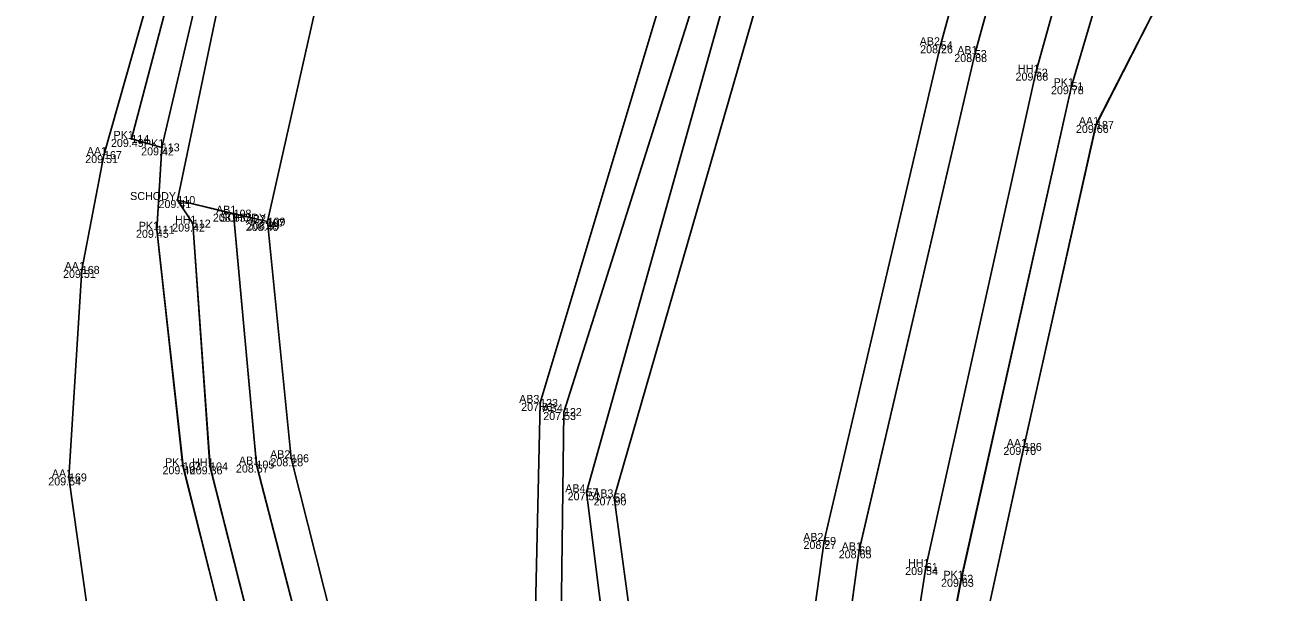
# Model space of a CAD drawing. Extents: x -262982 to -262706, y -1238714 to -1237093.
# Drawn here: x -262957.98 to -262926.85, y -1238375.85 to -1238361.66 of the extents above; entities that cross this region are included whole.
import ezdxf

# ---------------------------------------------------------------- set-up
doc = ezdxf.new("R2010")
doc.units = 0
for name, color, linetype in [('01_Hrana_betónu', 7, 'Continuous'), ('02_Oplotenie', 7, 'Continuous'), ('03_Asfalt', 7, 'Continuous'), ('05_Hrana_terénu', 7, 'Continuous'), ('06_Schody', 7, 'Continuous'), ('Groma (21)', 7, 'Continuous'), ('Groma (22)', 7, 'Continuous'), ('Groma (23)', 7, 'Continuous'), ('Groma (24)', 7, 'Continuous'), ('U002_Asfalt', 7, 'Continuous'), ('U002_Betónové panely', 7, 'Continuous'), ('U002_Schody', 7, 'Continuous'), ('U002_Zeleň_mimo', 7, 'Continuous'), ('U002_Zeleň_vnútro', 7, 'Continuous'), ('U002_Zeleň_zatrávňovač', 7, 'Continuous')]:
    doc.layers.add(name, color=color, linetype=linetype)

msp = doc.modelspace()

# ---------------------------------------------------------------- linework, layer by layer
at = {"layer": '01_Hrana_betónu'}
for points in [[(-262944.213, -1238387.387), (-262944.634, -1238381.789), (-262944.5, -1238371.343), (-262941.2, -1238360.927), (-262935.086, -1238341.218), (-262927.632, -1238317.179), (-262920.793, -1238295.265), (-262911.171, -1238262.813), (-262915.352, -1238261.064), (-262915.337, -1238259.329), (-262909.866, -1238261.629), (-262904.904, -1238263.716)], [(-262916.095, -1238261.519), (-262911.974, -1238263.293), (-262921.591, -1238294.909), (-262928.534, -1238317.073), (-262935.896, -1238340.99), (-262941.971, -1238360.685), (-262945.096, -1238371.115), (-262945.34, -1238381.803), (-262945.412, -1238387.557)], [(-262941.714, -1238387.032), (-262942.991, -1238380.859), (-262943.934, -1238373.35), (-262940.485, -1238361.041), (-262934.456, -1238341.421), (-262927.277, -1238318.134), (-262920.116, -1238294.802), (-262913.64, -1238273.614), (-262910.214, -1238263.245), (-262905.769, -1238265.099), (-262904.904, -1238263.716)], [(-262905.769, -1238265.099), (-262909.81, -1238264.181), (-262912.956, -1238273.861), (-262919.396, -1238295.066), (-262926.538, -1238318.409), (-262933.693, -1238341.579), (-262939.683, -1238361.151), (-262943.246, -1238373.477), (-262942.259, -1238380.752), (-262940.526, -1238386.713)], [(-262905.769, -1238265.099), (-262909.014, -1238275.12), (-262915.393, -1238296.189), (-262922.597, -1238319.497), (-262929.796, -1238342.936), (-262935.083, -1238362.17), (-262937.995, -1238374.567), (-262938.788, -1238380.26), (-262939.46, -1238386.668), (-262940.526, -1238386.713), (-262940.498, -1238386.859)], [(-262940.36, -1238387.407), (-262939.388, -1238387.391), (-262938.822, -1238386.902), (-262937.88, -1238380.385), (-262937.119, -1238374.802), (-262934.23, -1238362.39), (-262928.952, -1238343.2), (-262921.717, -1238319.813), (-262915.107, -1238298.192), (-262908.208, -1238275.423), (-262904.855, -1238265.436)], [(-262945.333, -1238387.95), (-262946.617, -1238387.98), (-262947.712, -1238387.066), (-262949.402, -1238383.422), (-262952.187, -1238372.656), (-262952.759, -1238366.382)], [(-262951.91, -1238366.581), (-262951.321, -1238372.499), (-262948.634, -1238383.126), (-262947.098, -1238386.578), (-262946.426, -1238387.428), (-262945.412, -1238387.557)]]:
    msp.add_lwpolyline(points, dxfattribs=at)
at = {"layer": '02_Oplotenie'}
msp.add_lwpolyline([(-262939.39, -1238320.83), (-262941.19, -1238324.79), (-262946.68, -1238336.9), (-262951.035, -1238350.68), (-262953.195, -1238358.97), (-262953.815, -1238358.809), (-262955.312, -1238364.513), (-262954.553, -1238364.724), (-262954.681, -1238366.785), (-262954.024, -1238372.698), (-262953.142, -1238376.2), (-262951.104, -1238384.342), (-262949.016, -1238390.045), (-262944.443, -1238389.969), (-262936.906, -1238389.616), (-262935.581, -1238380.82), (-262934.566, -1238375.513), (-262931.812, -1238363.194), (-262926.159, -1238344.076), (-262918.903, -1238320.384), (-262912.242, -1238298.942), (-262905.326, -1238276.054), (-262902.598, -1238266.292), (-262902.107, -1238264.892)], dxfattribs=at)
at = {"layer": '03_Asfalt'}
msp.add_lwpolyline([(-262929.61, -1238361.054), (-262931.199, -1238364.162), (-262933.003, -1238372.216), (-262934.974, -1238381.221), (-262935.119, -1238384.027), (-262936.052, -1238388.803), (-262936.611, -1238390.144), (-262937.981, -1238391.744), (-262940.017, -1238393.235), (-262941.857, -1238393.766), (-262943.351, -1238393.675), (-262945.246, -1238393.033), (-262947.034, -1238391.969), (-262949.331, -1238390.232), (-262950.782, -1238388.665), (-262952.605, -1238386.269), (-262954.108, -1238383.642), (-262955.193, -1238380.77), (-262956.048, -1238377.869), (-262956.307, -1238376.99), (-262956.874, -1238372.978), (-262956.554, -1238367.788), (-262955.999, -1238364.917), (-262954.725, -1238360.416)], dxfattribs=at)
at = {"layer": '05_Hrana_terénu'}
msp.add_lwpolyline([(-262920.126, -1238320.151), (-262927.385, -1238343.686), (-262932.704, -1238362.854), (-262935.453, -1238375.219), (-262936.279, -1238380.57), (-262937.519, -1238387.253), (-262938.314, -1238388.733), (-262939.759, -1238389.403), (-262945.681, -1238389.45), (-262947.587, -1238388.865), (-262949.049, -1238387.288), (-262950.436, -1238384.21), (-262953.347, -1238372.702), (-262953.777, -1238366.63), (-262954.163, -1238366.041), (-262952.487, -1238358.01), (-262951.855, -1238357.25), (-262949.897, -1238349.853), (-262950.29, -1238348.92), (-262949.45, -1238345.83), (-262948.76, -1238345.496), (-262946.63, -1238339.15), (-262945.04, -1238334.12), (-262941.75, -1238326.63)], dxfattribs=at)
at = {"layer": '06_Schody'}
msp.add_lwpolyline([(-262951.91, -1238366.581), (-262952.759, -1238366.382), (-262954.163, -1238366.041), (-262952.487, -1238358.01), (-262950.921, -1238358.358), (-262950.104, -1238358.539)], close=True, dxfattribs=at)
at = {"layer": 'Groma (21)'}
for centre in [(-262935.083, -1238362.17), (-262934.23, -1238362.39), (-262932.704, -1238362.854), (-262931.812, -1238363.194), (-262931.199, -1238364.162), (-262955.312, -1238364.513), (-262954.553, -1238364.724), (-262955.999, -1238364.917), (-262954.163, -1238366.041), (-262953.777, -1238366.63), (-262952.759, -1238366.382), (-262951.932, -1238366.616), (-262951.91, -1238366.581), (-262954.681, -1238366.785), (-262956.554, -1238367.788), (-262945.096, -1238371.115), (-262944.5, -1238371.343), (-262933.003, -1238372.216), (-262951.321, -1238372.499), (-262954.024, -1238372.698), (-262953.347, -1238372.702), (-262952.187, -1238372.656), (-262956.874, -1238372.978), (-262943.934, -1238373.35), (-262943.246, -1238373.477), (-262937.995, -1238374.567), (-262937.119, -1238374.802), (-262935.453, -1238375.219), (-262934.566, -1238375.513)]:
    msp.add_circle(centre, 0.01, dxfattribs=at)
at = {"layer": 'U002_Asfalt'}
msp.add_lwpolyline([(-262962.63, -1238381.65), (-262956.048, -1238377.869), (-262955.19, -1238380.77), (-262954.11, -1238383.64), (-262952.61, -1238386.27), (-262950.78, -1238388.67), (-262949.33, -1238390.23), (-262947.03, -1238391.97), (-262945.25, -1238393.03), (-262943.35, -1238393.68), (-262941.86, -1238393.77), (-262940.02, -1238393.24), (-262937.98, -1238391.74), (-262936.61, -1238390.14), (-262936.05, -1238388.8), (-262935.12, -1238384.03), (-262934.97, -1238381.22), (-262933, -1238372.22), (-262931.2, -1238364.16), (-262929.61, -1238361.05)], dxfattribs=at)
at = {"layer": 'U002_Betónové panely'}
msp.add_lwpolyline([(-262928.95, -1238343.2), (-262934.23, -1238362.39), (-262937.12, -1238374.8), (-262937.88, -1238380.39), (-262938.82, -1238386.9), (-262939.39, -1238387.39), (-262940.36, -1238387.41), (-262940.41, -1238387.31), (-262940.5, -1238386.86), (-262941.71, -1238387.03), (-262944.21, -1238387.39), (-262945.41, -1238387.56), (-262945.33, -1238387.95), (-262946.62, -1238387.98), (-262947.71, -1238387.07), (-262949.4, -1238383.42), (-262952.19, -1238372.66), (-262952.76, -1238366.38), (-262951.91, -1238366.58), (-262950.1, -1238358.54)], dxfattribs=at)
at = {"layer": 'U002_Schody'}
msp.add_lwpolyline([(-262950.1, -1238358.54), (-262951.91, -1238366.58), (-262952.76, -1238366.38), (-262954.16, -1238366.04), (-262952.49, -1238358.01), (-262950.92, -1238358.36)], close=True, dxfattribs=at)
at = {"layer": 'U002_Zeleň_mimo'}
for points in [[(-262935.58, -1238380.82), (-262934.57, -1238375.51), (-262931.81, -1238363.19), (-262926.16, -1238344.08)], [(-262929.61, -1238361.05), (-262931.2, -1238364.16), (-262933, -1238372.22), (-262934.97, -1238381.22)]]:
    msp.add_lwpolyline(points, dxfattribs=at)
at = {"layer": 'U002_Zeleň_vnútro'}
for points in [[(-262918.9, -1238320.38), (-262926.16, -1238344.08), (-262931.81, -1238363.19), (-262934.57, -1238375.51), (-262935.58, -1238380.82), (-262936.91, -1238389.62), (-262944.44, -1238389.97), (-262949.02, -1238390.05), (-262951.1, -1238384.34), (-262954.02, -1238372.7), (-262954.68, -1238366.78), (-262954.55, -1238364.72), (-262953.2, -1238358.97), (-262951.03, -1238350.68), (-262946.68, -1238336.9), (-262941.19, -1238324.79)], [(-262952.49, -1238358.01), (-262954.16, -1238366.04), (-262953.78, -1238366.63), (-262953.35, -1238372.7), (-262950.44, -1238384.21), (-262949.05, -1238387.29), (-262947.59, -1238388.87), (-262945.68, -1238389.45), (-262939.76, -1238389.4), (-262938.31, -1238388.73), (-262937.52, -1238387.25), (-262936.28, -1238380.57), (-262935.45, -1238375.22), (-262932.7, -1238362.85), (-262927.39, -1238343.69)]]:
    msp.add_lwpolyline(points, dxfattribs=at)
at = {"layer": 'U002_Zeleň_zatrávňovač'}
for points in [[(-262937.88, -1238380.39), (-262937.12, -1238374.8), (-262934.23, -1238362.39), (-262928.95, -1238343.2)], [(-262927.39, -1238343.69), (-262932.7, -1238362.85), (-262935.45, -1238375.22), (-262936.28, -1238380.57)], [(-262950.44, -1238384.21), (-262953.35, -1238372.7), (-262953.78, -1238366.63), (-262954.16, -1238366.04), (-262952.76, -1238366.38), (-262952.19, -1238372.66), (-262949.4, -1238383.42)]]:
    msp.add_lwpolyline(points, dxfattribs=at)

# ---------------------------------------------------------------- texts
at = {"layer": 'Groma (22)'}
for s, p in [('54', (-262935.083, -1238362.27)), ('53', (-262934.23, -1238362.49)), ('52', (-262932.704, -1238362.954)), ('51', (-262931.812, -1238363.294)), ('187', (-262931.199, -1238364.262)), ('114', (-262955.312, -1238364.613)), ('113', (-262954.553, -1238364.824)), ('167', (-262955.999, -1238365.017)), ('110', (-262954.163, -1238366.141)), ('108', (-262952.759, -1238366.482)), ('112', (-262953.777, -1238366.73)), ('107', (-262951.932, -1238366.716)), ('109', (-262951.91, -1238366.681)), ('111', (-262954.681, -1238366.885)), ('168', (-262956.554, -1238367.888)), ('123', (-262945.096, -1238371.215)), ('122', (-262944.5, -1238371.443)), ('186', (-262933.003, -1238372.316)), ('105', (-262952.187, -1238372.756)), ('106', (-262951.321, -1238372.599)), ('169', (-262956.874, -1238373.078)), ('103', (-262954.024, -1238372.798)), ('104', (-262953.347, -1238372.802)), ('57', (-262943.934, -1238373.45)), ('58', (-262943.246, -1238373.577)), ('59', (-262937.995, -1238374.667)), ('60', (-262937.119, -1238374.902)), ('61', (-262935.453, -1238375.319)), ('62', (-262934.566, -1238375.613))]:
    msp.add_text(s, height=0.2, dxfattribs=at).set_placement(p)
at = {"layer": 'Groma (23)'}
for s, p in [('208.26', (-262935.595, -1238362.37)), ('208.68', (-262934.742, -1238362.59)), ('209.68', (-262933.211, -1238363.054)), ('209.78', (-262932.325, -1238363.394)), ('209.66', (-262931.701, -1238364.362)), ('209.49', (-262955.824, -1238364.713)), ('209.42', (-262955.07, -1238364.924)), ('209.51', (-262956.467, -1238365.117)), ('209.41', (-262954.636, -1238366.241)), ('209.42', (-262954.294, -1238366.83)), ('208.85', (-262953.276, -1238366.582)), ('208.40', (-262952.452, -1238366.816)), ('208.39', (-262952.422, -1238366.781)), ('209.45', (-262955.198, -1238366.985)), ('209.51', (-262957.022, -1238367.988)), ('207.81', (-262945.57, -1238371.315)), ('207.53', (-262945.017, -1238371.543)), ('209.70', (-262933.515, -1238372.416)), ('208.28', (-262951.838, -1238372.699)), ('209.46', (-262954.536, -1238372.898)), ('209.36', (-262953.854, -1238372.902)), ('208.67', (-262952.7, -1238372.856)), ('209.54', (-262957.391, -1238373.178)), ('207.51', (-262944.408, -1238373.55)), ('207.90', (-262943.758, -1238373.677)), ('208.27', (-262938.512, -1238374.767)), ('208.65', (-262937.631, -1238375.002)), ('209.54', (-262935.97, -1238375.419)), ('209.63', (-262935.073, -1238375.713))]:
    msp.add_text(s, height=0.2, dxfattribs=at).set_placement(p)
at = {"layer": 'Groma (24)'}
for s, p in [('AB2', (-262935.607, -1238362.17)), ('AB1', (-262934.668, -1238362.39)), ('HH1', (-262933.151, -1238362.854)), ('PK1', (-262932.259, -1238363.194)), ('AA1', (-262931.627, -1238364.162)), ('PK1', (-262955.759, -1238364.513)), ('AA1', (-262956.427, -1238364.917)), ('PK1', (-262955, -1238364.724)), ('SCHODY', (-262955.344, -1238366.041)), ('AB1', (-262953.197, -1238366.382)), ('PK1', (-262955.128, -1238366.785)), ('HH1', (-262954.224, -1238366.63)), ('SCHODY', (-262953.091, -1238366.581)), ('AB2', (-262952.456, -1238366.616)), ('AA1', (-262956.982, -1238367.788)), ('AB3', (-262945.62, -1238371.115)), ('AB4', (-262945.034, -1238371.343)), ('AA1', (-262933.431, -1238372.216)), ('PK1', (-262954.471, -1238372.698)), ('HH1', (-262953.794, -1238372.702)), ('AB1', (-262952.625, -1238372.656)), ('AB2', (-262951.845, -1238372.499)), ('AA1', (-262957.302, -1238372.978)), ('AB4', (-262944.468, -1238373.35)), ('AB3', (-262943.77, -1238373.477)), ('AB2', (-262938.519, -1238374.567)), ('AB1', (-262937.557, -1238374.802)), ('HH1', (-262935.9, -1238375.219)), ('PK1', (-262935.013, -1238375.513))]:
    msp.add_text(s, height=0.2, dxfattribs=at).set_placement(p)

doc.saveas('drawing.dxf')
